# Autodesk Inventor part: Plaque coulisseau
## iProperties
Author: Flavien MARTY
Shininess: 20.0
PropertySet Name: _Private Model Information
Created: 2001-10
Part Number: Plaque coulisseau
Material: Par défaut
Document SubType Name: Modélisation
Designer: Flavien MARTY
Control State: 0
Master: False
Checked Out: False
PropertySet Name: Design Tracking Control
Density: 0.0
Volumn: 0.0
Area: 0.0
PropertySet Name: Model Information
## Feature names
1. Base1
